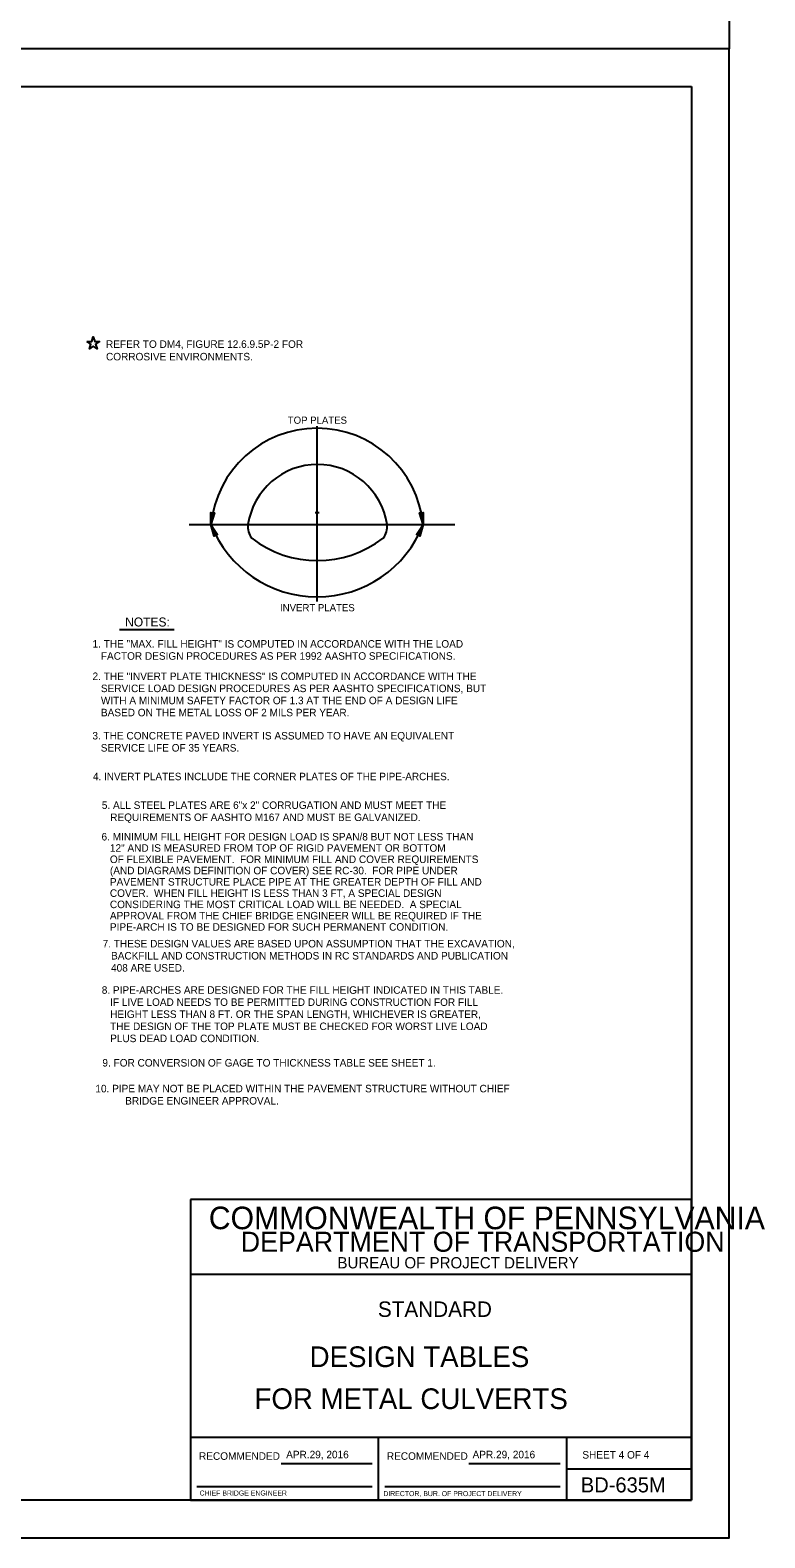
# Model space of a CAD drawing. Extents: x 591 to 2288, y -189 to 2187.
# Drawn here: x 1994 to 2288, y 405 to 1007 of the extents above; entities that cross this region are included whole.
import ezdxf

# ---------------------------------------------------------------- set-up
doc = ezdxf.new("R2010")
doc.units = 0
for name, color, linetype in [('1', 7, 'Continuous'), ('2', 7, 'Continuous'), ('PLT-BNDY', 7, 'Continuous')]:
    doc.layers.add(name, color=color, linetype=linetype)

msp = doc.modelspace()

# ---------------------------------------------------------------- linework, layer by layer
at = {"layer": '1'}
for p, q in [((2108.8, 778.77), (2108.8, 848.7)), ((2107.99, 814.24), (2109.63, 814.24)), ((2107.99, 814.24), (2109.63, 814.24)), ((2057.75, 809.48), (2163.8, 809.48)), ((2135.23, 804.06), (2135.14, 804.06)), ((2029.9, 767.54), (2051.69, 767.54)), ((2133.34, 420.21), (2133.34, 445.21)), ((2208.34, 445.21), (2208.34, 420.21)), ((2094.43, 434.93), (2130.84, 434.93)), ((2169.43, 434.93), (2205.84, 434.93)), ((2060.84, 425.71), (2130.84, 425.71)), ((2135.84, 425.71), (2205.84, 425.71))]:
    msp.add_line(p, q, dxfattribs=at)
for points in [[(2067.67, 813.89), (2067.32, 813.77), (2066.43, 809.48), (2067.67, 813.89), (2067.9, 814.09), (2066.43, 809.48), (2066.87, 813.84), (2066.57, 814.04), (2066.43, 809.48), (2066.39, 814.32), (2066.57, 814.04)], [(2151.04, 814.06), (2150.74, 813.84), (2151.16, 809.48), (2151.04, 814.06), (2151.21, 814.32), (2151.16, 809.48), (2150.3, 813.77), (2149.95, 813.88), (2151.16, 809.48), (2149.7, 814.09), (2149.95, 813.88)], [(2067.79, 805.11), (2068.02, 805.4), (2066.43, 809.48), (2067.79, 805.11), (2067.7, 804.82), (2066.43, 809.48), (2068.43, 805.59), (2068.79, 805.58), (2066.43, 809.48), (2069.1, 805.45), (2068.79, 805.58)], [(2148.76, 805.58), (2149.13, 805.6), (2151.16, 809.48), (2148.76, 805.58), (2148.49, 805.45), (2151.16, 809.48), (2149.55, 805.41), (2149.78, 805.13), (2151.16, 809.48), (2149.88, 804.82), (2149.78, 805.13)]]:
    msp.add_lwpolyline(points, dxfattribs=at)
for centre, radius, start, end in [((2108.8, 805.31), 42.57, 5.62409, 174.37591), ((2108.98, 805.38), 28.06, 8.43229, 171.58932), ((2108.8, 826.1), 45.51, 201.4219, 338.5781), ((2088.35, 808.53), 7.2, 172.36675, 218.49792), ((2129.6, 808.54), 7.2, 321.50208, 7.63325), ((2108.92, 837.8), 42.73, 232.17316, 307.84893)]:
    msp.add_arc(centre, radius, start, end, dxfattribs=at)
at = {"layer": '2'}
for p, q in [((1472.34, 984.21), (2258.34, 984.21)), ((2258.34, 984.21), (2258.34, 420.21)), ((2019.43, 881.7), (2019.43, 881.7)), ((2258.34, 540.21), (2058.34, 540.21)), ((2058.34, 540.21), (2058.34, 420.21)), ((2258.34, 420.21), (2258.34, 540.21)), ((2258.34, 510.21), (2058.34, 510.21)), ((2258.34, 445.21), (2058.34, 445.21)), ((2208.34, 432.71), (2258.34, 432.71)), ((2258.34, 420.21), (1472.34, 420.21)), ((2058.34, 420.21), (2258.34, 420.21))]:
    msp.add_line(p, q, dxfattribs=at)
msp.add_lwpolyline([(2016.94, 882.51), (2018.86, 882.5), (2019.45, 884.34), (2020.04, 882.49), (2021.97, 882.51), (2020.39, 881.37), (2021.01, 879.55), (2019.44, 880.69), (2017.89, 879.55), (2018.49, 881.38), (2016.94, 882.51)], dxfattribs=at)
at = {"layer": 'PLT-BNDY'}
for points in [[(1432.34, 1593.21), (2273.34, 1593.21), (2273.34, 999.21), (1432.34, 999.21)], [(1432.34, 405.21), (2273.34, 405.21), (2273.34, 999.21), (1432.34, 999.21)]]:
    msp.add_lwpolyline(points, close=True, dxfattribs=at)

# ---------------------------------------------------------------- texts
at = {"layer": '1'}
for s, height, p in [('TOP PLATES', 2.866, (2097.11, 849.68)), ('INVERT PLATES', 2.8664, (2094.02, 774.87)), ('NOTES:', 3.583, (2032.19, 768.8)), ('  1. THE "MAX. FILL HEIGHT" IS COMPUTED IN ACCORDANCE WITH THE LOAD ', 3, (2016.92, 760.36)), ('     FACTOR DESIGN PROCEDURES AS PER 1992 AASHTO SPECIFICATIONS.', 3, (2016.92, 755.53)), ('  2. THE "INVERT PLATE THICKNESS" IS COMPUTED IN ACCORDANCE WITH THE', 3, (2016.94, 747.44)), ('     WITH A MINIMUM SAFETY FACTOR OF 1.3 AT THE END OF A DESIGN LIFE ', 3, (2016.94, 737.79)), ('     SERVICE LOAD DESIGN PROCEDURES AS PER AASHTO SPECIFICATIONS, BUT ', 3, (2016.94, 742.61)), ('     BASED ON THE METAL LOSS OF 2 MILS PER YEAR.', 3, (2016.94, 732.97)), ('  3. THE CONCRETE PAVED INVERT IS ASSUMED TO HAVE AN EQUIVALENT', 3, (2016.88, 723.72)), ('     SERVICE LIFE OF 35 YEARS.', 3, (2016.88, 718.9)), ('5. ALL STEEL PLATES ARE 6"x 2" CORRUGATION AND MUST MEET THE', 3, (2022.88, 696.02)), ('   REQUIREMENTS OF AASHTO M167 AND MUST BE GALVANIZED.', 3, (2022.88, 691.19)), ('7. THESE DESIGN VALUES ARE BASED UPON ASSUMPTION THAT THE EXCAVATION,', 3, (2023.21, 640.76)), ('   BACKFILL AND CONSTRUCTION METHODS IN RC STANDARDS AND PUBLICATION', 3, (2023.21, 635.94)), ('   408 ARE USED.', 3, (2023.21, 631.11)), ('8. PIPE-ARCHES ARE DESIGNED FOR THE FILL HEIGHT INDICATED IN THIS TABLE.', 3, (2022.85, 622.27)), ('   IF LIVE LOAD NEEDS TO BE PERMITTED DURING CONSTRUCTION FOR FILL', 3, (2022.85, 617.44)), ('   HEIGHT LESS THAN 8 FT. OR THE SPAN LENGTH, WHICHEVER IS GREATER,', 3, (2022.85, 612.62)), ('   THE DESIGN OF THE TOP PLATE MUST BE CHECKED FOR WORST LIVE LOAD', 3, (2022.85, 607.79)), ('   PLUS DEAD LOAD CONDITION.', 3, (2022.85, 602.97)), ('9. FOR CONVERSION OF GAGE TO THICKNESS TABLE SEE SHEET 1.', 3, (2023.1, 593.24)), ('RECOMMENDED', 3, (2061.67, 436.34)), ('RECOMMENDED', 3, (2136.67, 436.34)), ('CHIEF BRIDGE ENGINEER', 2.0003, (2061.93, 422.09)), ('DIRECTOR, BUR. OF PROJECT DELIVERY', 2.0003, (2135.25, 421.86))]:
    msp.add_text(s, height=height, dxfattribs=at).set_placement(p)
at = {"layer": '2'}
for s, height, p in [('REFER TO DM4, FIGURE 12.6.9.5P-2 FOR', 3, (2024.54, 879.96)), ('CORROSIVE ENVIRONMENTS.', 3, (2024.54, 874.96)), ('  4. INVERT PLATES INCLUDE THE CORNER PLATES OF THE PIPE-ARCHES.', 2.97, (2017.13, 707.48)), ('6. MINIMUM FILL HEIGHT FOR DESIGN LOAD IS SPAN/8 BUT NOT LESS THAN', 3, (2022.76, 683.43)), ('   12" AND IS MEASURED FROM TOP OF RIGID PAVEMENT OR BOTTOM', 3, (2022.76, 678.93)), ('   OF FLEXIBLE PAVEMENT.  FOR MINIMUM FILL AND COVER REQUIREMENTS ', 3, (2022.76, 674.43)), ('   (AND DIAGRAMS DEFINITION OF COVER) SEE RC-30.  FOR PIPE UNDER', 3, (2022.76, 669.93)), ('   PAVEMENT STRUCTURE PLACE PIPE AT THE GREATER DEPTH OF FILL AND', 3, (2022.76, 665.43)), ('   COVER.  WHEN FILL HEIGHT IS LESS THAN 3 FT, A SPECIAL DESIGN', 3, (2022.76, 660.93)), ('   CONSIDERING THE MOST CRITICAL LOAD WILL BE NEEDED.  A SPECIAL', 3, (2022.76, 656.43)), ('   APPROVAL FROM THE CHIEF BRIDGE ENGINEER WILL BE REQUIRED IF THE', 3, (2022.76, 651.93)), ('   PIPE-ARCH IS TO BE DESIGNED FOR SUCH PERMANENT CONDITION.', 3, (2022.76, 647.43)), ('10. PIPE MAY NOT BE PLACED WITHIN THE PAVEMENT STRUCTURE WITHOUT CHIEF', 3, (2020.31, 582.95)), ('BRIDGE ENGINEER APPROVAL.', 3, (2032.22, 578.08)), ('COMMONWEALTH OF PENNSYLVANIA', 9, (2065.59, 528.34)), ('DEPARTMENT OF TRANSPORTATION', 8.0002, (2078.34, 519.34)), ('BUREAU OF PROJECT DELIVERY', 4.5, (2116.93, 512.71)), ('STANDARD', 6.188, (2133.09, 493.34)), ('DESIGN TABLES', 8.2515, (2105.84, 473.34)), ('FOR METAL CULVERTS', 8.2515, (2083.84, 456.59)), ('APR.29, 2016', 3, (2096.47, 436.95)), ('APR.29, 2016', 3, (2170.89, 436.95)), ('SHEET 4 OF 4', 3, (2214.71, 436.84)), ('BD-635M', 6, (2214.09, 423.34))]:
    msp.add_text(s, height=height, dxfattribs=at).set_placement(p)

doc.saveas('drawing.dxf')
